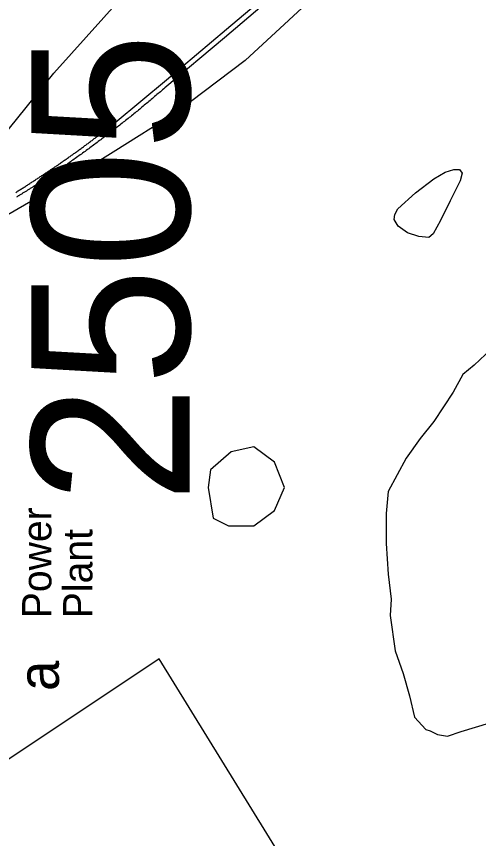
# Model space of a CAD drawing. Extents: x 1373043 to 1375788, y 550128 to 553055.
# Drawn here: x 1373392.9 to 1373433.7, y 550759.4 to 550832 of the extents above; entities that cross this region are included whole.
import ezdxf

# ---------------------------------------------------------------- set-up
doc = ezdxf.new("R2010")
doc.units = 0
for name, color, linetype in [('Old_Level_12', 7, 'Continuous'), ('Old_Level_22', 7, 'Continuous'), ('Old_Level_32', 7, 'Continuous'), ('Old_Level_44', 7, 'Continuous'), ('Old_Level_48', 7, 'Continuous'), ('Old_Level_59', 7, 'Continuous'), ('Old_Level_62', 7, 'Continuous')]:
    doc.layers.add(name, color=color, linetype=linetype)

msp = doc.modelspace()

# ---------------------------------------------------------------- linework, layer by layer
at = {"layer": 'Old_Level_32'}
for points in [[(1373312.503, 550789.888), (1373315.409, 550791.382), (1373319.747, 550792.767), (1373327.67, 550794.971), (1373334.41, 550797.08), (1373339.304, 550798.669), (1373343.713, 550800.126), (1373350.282, 550802.367), (1373366.35, 550807.53), (1373371.485, 550809.055), (1373378.054, 550811.225), (1373381.153, 550812.178), (1373385.117, 550814.728), (1373386.584, 550815.987), (1373388.24, 550817.281), (1373391.434, 550821.072), (1373396.236, 550827.007), (1373405.034, 550836.861), (1373410.471, 550842.938), (1373418.291, 550852.163), (1373421.651, 550856.004)], [(1373431.603, 550845.243), (1373413.092, 550828.113), (1373407.08, 550823.547), (1373401.46, 550820.021), (1373398.405, 550818.112), (1373388.839, 550812.593), (1373382.95, 550809.402), (1373381.154, 550808.504), (1373378.758, 550807.806), (1373371.971, 550805.013), (1373361.505, 550800.984), (1373351.424, 550797.143)]]:
    msp.add_lwpolyline(points, dxfattribs=at)
at = {"layer": 'Old_Level_44'}
for points in [[(1373401.623, 550822.642), (1373406.176, 550826.404), (1373411.46, 550830.887), (1373419.143, 550837.382), (1373445.513, 550859.747), (1373468.681, 550879.45)], [(1373469.683, 550879.751), (1373463.721, 550874.577), (1373452.178, 550864.84), (1373436.463, 550851.508), (1373424.554, 550841.416), (1373411.29, 550830.125), (1373406.021, 550825.713)], [(1373406.021, 550825.713), (1373405.92, 550825.626), (1373405.819, 550825.539), (1373405.719, 550825.452), (1373405.621, 550825.365), (1373405.521, 550825.277), (1373405.421, 550825.193), (1373405.321, 550825.106), (1373405.217, 550825.019), (1373405.117, 550824.932), (1373405.017, 550824.845), (1373404.917, 550824.764), (1373404.813, 550824.677), (1373404.713, 550824.589), (1373404.613, 550824.502), (1373404.512, 550824.422), (1373404.408, 550824.334), (1373404.308, 550824.25), (1373404.206, 550824.163), (1373404.103, 550824.079), (1373404.003, 550823.995), (1373403.901, 550823.908), (1373403.798, 550823.827), (1373403.696, 550823.743), (1373403.593, 550823.656), (1373403.491, 550823.572), (1373403.389, 550823.491), (1373403.284, 550823.404), (1373403.183, 550823.32), (1373403.079, 550823.24), (1373402.976, 550823.156), (1373402.873, 550823.075), (1373402.769, 550822.991), (1373402.666, 550822.907), (1373402.562, 550822.826), (1373402.459, 550822.742), (1373402.356, 550822.661), (1373402.251, 550822.577), (1373402.146, 550822.493), (1373402.044, 550822.413), (1373401.939, 550822.329), (1373401.836, 550822.251), (1373401.731, 550822.167), (1373401.624, 550822.087), (1373401.521, 550822.006), (1373401.416, 550821.925), (1373401.311, 550821.841), (1373401.208, 550821.764), (1373401.101, 550821.68), (1373400.996, 550821.602), (1373400.89, 550821.518), (1373400.786, 550821.441), (1373400.68, 550821.36), (1373400.575, 550821.279), (1373400.47, 550821.198), (1373400.363, 550821.121), (1373400.257, 550821.043), (1373400.15, 550820.959), (1373400.045, 550820.882), (1373399.94, 550820.801), (1373399.834, 550820.724), (1373399.725, 550820.643), (1373399.619, 550820.565), (1373399.512, 550820.488), (1373399.406, 550820.407), (1373399.299, 550820.33), (1373399.191, 550820.249), (1373399.084, 550820.171), (1373398.979, 550820.097), (1373398.871, 550820.02), (1373398.765, 550819.939), (1373398.656, 550819.861), (1373398.548, 550819.787), (1373398.442, 550819.706), (1373398.333, 550819.632), (1373398.225, 550819.555), (1373398.117, 550819.474), (1373398.009, 550819.4), (1373397.899, 550819.325), (1373397.791, 550819.248), (1373397.683, 550819.17), (1373397.574, 550819.093), (1373397.466, 550819.018), (1373397.358, 550818.944), (1373397.248, 550818.87), (1373397.14, 550818.792), (1373397.032, 550818.715), (1373396.922, 550818.641), (1373396.812, 550818.566), (1373396.702, 550818.492), (1373396.594, 550818.415), (1373396.484, 550818.34), (1373396.376, 550818.266), (1373396.266, 550818.192), (1373396.155, 550818.121), (1373396.045, 550818.046), (1373395.935, 550817.972), (1373395.824, 550817.895), (1373395.714, 550817.824), (1373395.604, 550817.749)], [(1373394.745, 550817.678), (1373394.816, 550817.727), (1373394.889, 550817.775), (1373394.96, 550817.82), (1373395.033, 550817.866), (1373395.104, 550817.911), (1373395.176, 550817.959), (1373395.248, 550818.008), (1373395.319, 550818.053), (1373395.391, 550818.101), (1373395.462, 550818.146), (1373395.533, 550818.195), (1373395.604, 550818.243), (1373395.677, 550818.289), (1373395.748, 550818.337), (1373395.819, 550818.385), (1373395.89, 550818.434), (1373395.961, 550818.482), (1373396.034, 550818.531), (1373396.105, 550818.576), (1373396.174, 550818.624), (1373396.245, 550818.673), (1373396.316, 550818.721), (1373396.388, 550818.77), (1373396.459, 550818.818), (1373396.53, 550818.863), (1373396.601, 550818.915), (1373396.669, 550818.964), (1373396.74, 550819.009), (1373396.811, 550819.06), (1373396.882, 550819.109), (1373396.953, 550819.161), (1373397.022, 550819.206), (1373397.093, 550819.254), (1373397.163, 550819.306), (1373397.234, 550819.354), (1373397.303, 550819.403), (1373397.374, 550819.451), (1373397.445, 550819.503), (1373397.513, 550819.548), (1373397.584, 550819.6), (1373397.654, 550819.648), (1373397.725, 550819.7), (1373397.794, 550819.752), (1373397.863, 550819.797), (1373397.933, 550819.848), (1373398.002, 550819.9), (1373398.073, 550819.949), (1373398.141, 550819.997), (1373398.212, 550820.049), (1373398.282, 550820.097), (1373398.351, 550820.149), (1373398.419, 550820.2), (1373398.49, 550820.249), (1373398.559, 550820.297), (1373398.629, 550820.349), (1373398.697, 550820.401), (1373398.766, 550820.452), (1373398.836, 550820.504), (1373398.903, 550820.553), (1373398.973, 550820.604), (1373399.042, 550820.656), (1373399.11, 550820.708), (1373399.179, 550820.756), (1373399.249, 550820.804), (1373399.317, 550820.856), (1373399.386, 550820.908), (1373399.456, 550820.963), (1373399.523, 550821.014), (1373399.593, 550821.066), (1373399.659, 550821.118), (1373399.729, 550821.169), (1373399.798, 550821.218), (1373399.866, 550821.269), (1373399.934, 550821.321), (1373400.003, 550821.373), (1373400.071, 550821.428), (1373400.139, 550821.479), (1373400.206, 550821.531), (1373400.274, 550821.583), (1373400.342, 550821.638), (1373400.41, 550821.689), (1373400.479, 550821.738), (1373400.546, 550821.789), (1373400.615, 550821.844), (1373400.681, 550821.896), (1373400.749, 550821.951), (1373400.817, 550822.003), (1373400.885, 550822.054), (1373400.951, 550822.109), (1373401.019, 550822.161), (1373401.087, 550822.216), (1373401.154, 550822.267), (1373401.221, 550822.322), (1373401.288, 550822.374), (1373401.355, 550822.429), (1373401.422, 550822.481), (1373401.489, 550822.535), (1373401.556, 550822.584), (1373401.623, 550822.642)], [(1373392.875, 550816.474), (1373392.948, 550816.522), (1373393.021, 550816.57), (1373393.093, 550816.612), (1373393.166, 550816.661), (1373393.237, 550816.703), (1373393.31, 550816.751), (1373393.384, 550816.793), (1373393.453, 550816.842), (1373393.528, 550816.887), (1373393.6, 550816.932), (1373393.671, 550816.977), (1373393.744, 550817.026), (1373393.815, 550817.074), (1373393.888, 550817.116), (1373393.959, 550817.165), (1373394.032, 550817.21), (1373394.103, 550817.258), (1373394.172, 550817.307), (1373394.246, 550817.349), (1373394.316, 550817.397), (1373394.39, 550817.442), (1373394.459, 550817.491), (1373394.531, 550817.536), (1373394.602, 550817.585), (1373394.674, 550817.633), (1373394.745, 550817.678)], [(1373395.604, 550817.749), (1373395.551, 550817.714), (1373395.496, 550817.678), (1373395.443, 550817.643), (1373395.388, 550817.607), (1373395.335, 550817.572), (1373395.28, 550817.536), (1373395.226, 550817.501), (1373395.172, 550817.468), (1373395.118, 550817.433), (1373395.063, 550817.397), (1373395.007, 550817.362), (1373394.955, 550817.326), (1373394.899, 550817.291), (1373394.844, 550817.258), (1373394.791, 550817.223), (1373394.736, 550817.187), (1373394.681, 550817.152), (1373394.627, 550817.116), (1373394.573, 550817.081), (1373394.518, 550817.045), (1373394.463, 550817.013), (1373394.409, 550816.977), (1373394.355, 550816.942), (1373394.3, 550816.906), (1373394.243, 550816.871), (1373394.19, 550816.835), (1373394.135, 550816.806), (1373394.08, 550816.771), (1373394.025, 550816.735), (1373393.97, 550816.7), (1373393.915, 550816.667), (1373393.862, 550816.632), (1373393.807, 550816.596), (1373393.752, 550816.564), (1373393.696, 550816.528), (1373393.641, 550816.493), (1373393.586, 550816.457), (1373393.531, 550816.428), (1373393.476, 550816.393), (1373393.421, 550816.357), (1373393.366, 550816.325), (1373393.31, 550816.289), (1373393.255, 550816.254), (1373393.2, 550816.222), (1373393.145, 550816.186), (1373393.09, 550816.157), (1373393.035, 550816.122), (1373392.98, 550816.086), (1373392.925, 550816.054)]]:
    msp.add_lwpolyline(points, dxfattribs=at)
at = {"layer": 'Old_Level_48'}
msp.add_lwpolyline([(1373417.885, 550755.2), (1373405.508, 550775.31), (1373351.12, 550739.005)], dxfattribs=at)
at = {"layer": 'Old_Level_59'}
msp.add_lwpolyline([(1373435.294, 550803.098), (1373433.316, 550801.212), (1373432.318, 550800.406), (1373431.459, 550798.85), (1373429.752, 550796.24), (1373428.533, 550794.751), (1373427.309, 550793.014), (1373425.725, 550790.081), (1373425.557, 550788.134), (1373425.555, 550785.483), (1373425.707, 550782.77), (1373425.972, 550780.558), (1373425.884, 550779.141), (1373426.333, 550775.997), (1373427.052, 550774.021), (1373427.592, 550772.045), (1373428.041, 550770.159), (1373429.03, 550769.081), (1373429.436, 550768.954), (1373430.075, 550768.624), (1373430.95, 550768.479), (1373432.149, 550768.899), (1373434.697, 550769.661)], dxfattribs=at)
at = {"layer": 'Old_Level_62'}
for points in [[(1373426.585, 550815.017), (1373428.139, 550816.435), (1373429.74, 550817.662), (1373430.759, 550818.273), (1373431.515, 550818.505), (1373432.006, 550818.496), (1373432.258, 550818.179), (1373432.062, 550817.488), (1373431.2, 550815.741), (1373430.338, 550813.993), (1373429.694, 550812.811), (1373429.3, 550812.501), (1373428.423, 550812.585), (1373427.422, 550812.918), (1373426.606, 550813.503), (1373426.256, 550814.081), (1373426.315, 550814.517), (1373426.585, 550815.017)], [(1373411.633, 550787.05), (1373413.881, 550787.05), (1373415.678, 550788.397), (1373416.577, 550790.419), (1373415.678, 550792.664), (1373413.881, 550794.012), (1373411.858, 550793.563), (1373410.06, 550791.991), (1373409.836, 550790.419), (1373410.285, 550787.724), (1373411.633, 550787.05)]]:
    msp.add_lwpolyline(points, dxfattribs=at)

# ---------------------------------------------------------------- texts
at = {"layer": 'Old_Level_12'}
msp.add_text('2505', height=13.9517, rotation=90, dxfattribs=at).set_placement((1373408.196, 550789.048))
at = {"layer": 'Old_Level_22'}
for s, height, p in [('Power', 2.5837, (1373396.01, 550778.885)), ('Plant', 2.5837, (1373399.627, 550778.885)), ('a', 3.617, (1373396.676, 550772.464))]:
    msp.add_text(s, height=height, rotation=90, dxfattribs=at).set_placement(p)

doc.saveas('drawing.dxf')
